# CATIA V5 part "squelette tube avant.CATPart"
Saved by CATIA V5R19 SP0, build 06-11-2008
Part number: squelette tube avant
Property "demi_longueur du guidon": 150 mm
Publications: "Plan.1", "Plan.2", "Plan.3", "Point.1", "Droite.1", "Plan.4", "Point.2", "Droite.2", "Droite.3", "longueur du tube", "position horizontale du guidon", "position verticale du guidon", "hauteur de la liaison pivot", "rayon interieur du tube avant", "demi_longueur du guidon", "rayon exterieur du support du guidon", "rayon interieur du support du guidon", "demi_longeur du support de guidon", "rayon du guidon"
Bounding box of the stored display mesh (mm): x -120 to 0, y -300 to 300, z 0 to 450
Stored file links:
  I:\yyang\yyang\squelette tube avant.CATPart
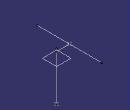
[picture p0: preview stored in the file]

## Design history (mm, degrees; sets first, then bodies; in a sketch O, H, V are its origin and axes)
Parameters
  `longueur du tube` = 450 mm
  `position horizontale du guidon` = 120 mm
  `position verticale du guidon` = 425 mm {= `longueur du tube`-25mm}
  `hauteur de la liaison pivot` = 370 mm {= `longueur du tube`-80mm}
  `rayon interieur du tube avant` = 15 mm
  `demi_longueur du guidon` = 300 mm
  `rayon interieur du support du guidon` = 12 mm
  `rayon exterieur du support du guidon` = 15 mm
  `demi_longeur du support de guidon` = 150 mm
  `rayon du guidon` = 20 mm
Body1 (main body)
  Plane1: type Offset, Offset 0, RefPlane xy-plane
  Plane2: type Offset, Offset 0, RefPlane yz-plane
  Plane3: type Offset, Offset 0, RefPlane zx-plane
  Point1: (0, 0, 0)
  Line1: type PtDir, Direction (0, 0, 1), Start 0, End 450 {= `longueur du tube`}, RefPoint Point1
  Plane4: type Offset, Offset 370 {= `hauteur de la liaison pivot`}, RefPlane Plane1
  Point2: (-120 {= -`position horizontale du guidon`}, 0, 425 {= `position verticale du guidon`})
  Line2: type PtDir, LineFirstUpto Line1, Direction (1, 0, 0), Start 0, End 0, RefPoint Point2
  Line3: type PtDir, Direction (0, 1, 0), Start -300, End 300 {= `demi_longueur du guidon`}, RefPoint Point2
